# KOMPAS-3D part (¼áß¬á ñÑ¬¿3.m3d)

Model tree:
1. Эскиз:1
2. Операция выдавливания:24
     Толщина стенки 2 = 10; Расстояние 1 = 0.6
3. Эскиз:22
4. Операция выдавливания:25
     Толщина стенки 1 = 6; Толщина стенки 2 = 6; Расстояние 1 = 0.6
5. Эскиз:23
6. Операция выдавливания:26
     Толщина стенки 1 = 6; Толщина стенки 2 = 6; Расстояние 1 = 0.6
7. Эскиз:24
8. Операция выдавливания:27
     Толщина стенки 1 = 6; Толщина стенки 2 = 6; Расстояние 1 = 0.6
9. Эскиз:25
10. Вырезать элемент выдавливания:10
     Расстояние 1 = 10
